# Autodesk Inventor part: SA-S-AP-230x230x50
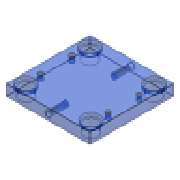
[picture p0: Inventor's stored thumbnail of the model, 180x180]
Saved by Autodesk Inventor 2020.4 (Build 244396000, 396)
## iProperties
Created: 2019-01
Part Number: SA-S-AP-230x230x50
Material: S 55 C
Description: Cavity Plate
Document SubType Name: Modeling
Designer: mel
Standard Revision: 1
Manufacturer: FUTABA
Language: fr-FR
Size Designation: 230x230x50
Categories: <MemberInstance><Categories><Category DisplayName="Moule" InternalName="349578f2-f4d4-4954-8c09-8e99297a61c0" Mnemonic="MOLD"><Category DisplayName="Plaque de m
Density: 7.85 g/cm^3
Appearance: Clear - Blue
IsCustomPart: 1
Author: mel
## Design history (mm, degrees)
sketch "Sketch1"
  geometry: L1 (-115, 115)-(115, 115); L2 (115, 115)-(115, -115); L3 (115, -115)-(-115, -115); L4 (-115, -115)-(-115, 115); 3 further points
  constraints: 8 end point, 2 midpoint, 2 parallel, 1 horizontal, 1 horizontal alignment, 1 perpendicular, 1 vertical alignment
  dimensions: "d123" = 230 distance between parallel lines of L2 L4 (= W_); "d124" = 230 distance between parallel lines of L3 L1 (= L)
extrude "Extrusion1" new body sketch "Sketch1" distance "d20" = 50 (= H_); taper "d30" = 0 deg
sketch "Sketch2"
  geometry: 4 further points
  constraints: 1 horizontal alignment
  dimensions: "d125" = 92.5 horizontal distance of point (0, 0) point (-92.5, 53) (= 0.5 x S1_W); "d126" = 53 vertical distance of point (0, 0) point (-92.5, 53) (= 0.5 x S1_L); "d127" = 92 horizontal distance of point (0, 0) point (-92, 92) (= 0.5 x GB_W); "d128" = 92 horizontal distance of point (0, 0) point (-92, 92) (= 0.5 x GB_L); "d129" = 92 horizontal distance of point (0, 0) point (92, 92) (= 0.5 x GB_W)
sketch "Sketch3"
  geometry: L1 (230, 0)-(0, 0) reference; 3 further points
  constraints: 1 midpoint, 1 vertical alignment
  dimensions: "d169" = 25 distance from line of L1 point (115, 25) (= 0.5 x H_)
hole "Hole1" sketch "Sketch3" at (115, 25) diameter "d170" = 13.835; stored, may be unused: countersink angle "d174" = 90 deg, drill point angle "d176" = 118 deg; dims "d171" = 29 (= le), "d172" = 4, "d173" = 2, "d175" = 39 (= ke)
sketch "Sketch4"
  geometry: L1 (0, 0)-(230, 0) reference; 4 further points
  constraints: 2 midpoint, 2 vertical alignment
  dimensions: "d177" = 25 distance from line of L1 point (115, -25) (= 0.5 x H_)
hole "Hole2" sketch "Sketch4" at (115, -25) diameter "d178" = 13.835; stored, may be unused: countersink angle "d182" = 90 deg, drill point angle "d184" = 118 deg; dims "d179" = 29 (= le), "d180" = 4, "d181" = 2, "d183" = 39 (= ke)
hole "Hole3" sketch "Sketch2" diameter "d130" = 30 (= GB_d1); stored, may be unused: countersink angle "d134" = 90 deg, drill point angle "d136" = 0 deg; dims "d131" = 6, "d132" = 36 (= GB_d2), "d133" = 8 (= GB_k), "d135" = 50 (= H_)
pattern_linear "Rectangular Pattern1" dims "d159" = 184 (computed from GB_L, Nl)
hole "Hole4" sketch "Sketch2" diameter "d137" = 30 (= GB_d1); stored, may be unused: countersink angle "d141" = 90 deg, drill point angle "d143" = 0 deg; dims "d138" = 6, "d139" = 36 (= GB_d2), "d140" = 8 (= GB_k), "d142" = 50 (= H_)
pattern_linear "Rectangular Pattern2" dims "d162" = 182 (computed from GB_L2, GB_L1, Nl)
hole "Hole5" sketch "Sketch2" diameter "d144" = 10.106; stored, may be unused: countersink angle "d148" = 90 deg, drill point angle "d150" = 118 deg; dims "d145" = 15 (= H_l), "d146" = 36 (= GB_d2), "d147" = 8 (= GB_k), "d149" = 24 (= H_u)
pattern_linear "Rectangular Pattern3" dims "d153" = 106 (computed from S1_L, Ns), "d156" = 185 (computed from S1_W, Nw)
chamfer "Chamfer1" distance "d185" = 0.5; stored, may be unused: second distance "d186" = 2, angle "d187" = 45 deg
feature "Sculpter2"
body "Solid1"
feature "Surface2"
body "Srf2"
other parameters: "L" = 230 [user parameter; used in 1 equation term], "W_" = 230 [user parameter; used in 1 equation term], "H_" = 50 [user parameter; used in 5 equation terms], "GB_W" = 184 [user parameter; used in 2 equation terms], "GB_d1" = 30 [user parameter; used in 2 equation terms], "GB_d2" = 36 [user parameter; used in 3 equation terms], "GB_k" = 8 [user parameter; used in 3 equation terms], "S1_L" = 106 [user parameter; used in 2 equation terms], "S1_W" = 185 [user parameter; used in 2 equation terms], "GB_L1" = 92 [user parameter; used in 1 equation term], "GB_L" = 184 [user parameter; used in 2 equation terms], "le" = 29 [user parameter; used in 2 equation terms], "ke" = 39 [user parameter; used in 2 equation terms], "H_l" = 15 [user parameter; used in 1 equation term], "H_u" = 24 [user parameter; used in 1 equation term]
